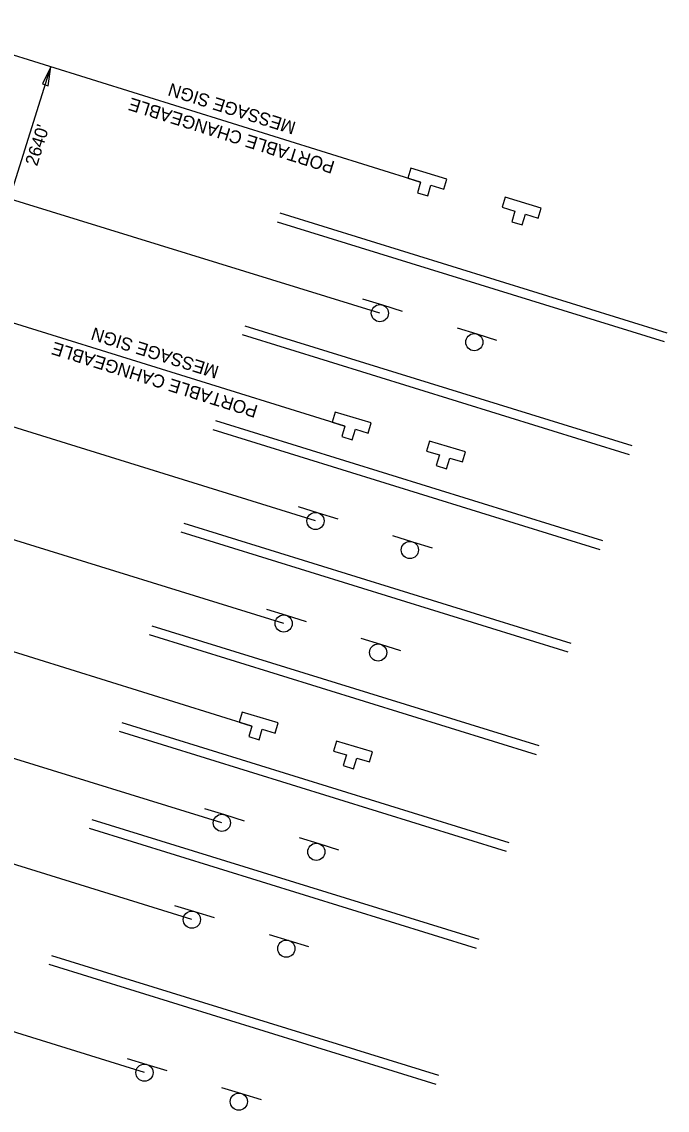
# Model space of a CAD drawing. Extents: x 2135767 to 2151731, y 141839 to 175894.
# Drawn here: x 2151203 to 2151504, y 148873 to 149380 of the extents above; entities that cross this region are included whole.
import ezdxf

# ---------------------------------------------------------------- set-up
doc = ezdxf.new("R2010")
doc.units = 0
for name, color, linetype in [('Default', 7, 'Continuous'), ('PR_Dimensions', 7, 'Continuous'), ('PR_Dimensions_Phase', 7, 'Continuous'), ('PR_Traffic_Control_Devices_Temp', 7, 'Continuous'), ('PR_Traffic_Sign_Temp', 7, 'Continuous'), ('PR_Txt', 7, 'Continuous')]:
    doc.layers.add(name, color=color, linetype=linetype)

# ---------------------------------------------------------------- blocks, each defined once
blk = doc.blocks.new('Arrowhd')
at = {"layer": 'Default'}
blk.add_lwpolyline([(0.318, -0.053), (0.318, 0.053), (0, 0)], close=True, dxfattribs=at)
blk = doc.blocks.new('PR-TCSIGN_rev')
at = {"layer": 'Default'}
blk.add_lwpolyline([(-5.47, 0), (-1.58, 0), (-1.58, -3.22), (1.58, -3.22), (1.58, 0), (5.47, 0), (5.47, 3.06), (-5.47, 3.06)], close=True, dxfattribs=at)
blk.add_lwpolyline([(1.58, 0), (5.47, 0), (5.47, 3.06), (-5.47, 3.06), (-5.47, 0), (-1.58, 0), (-1.58, -3.22), (1.58, -3.22), (1.58, 0)], dxfattribs=at)

msp = doc.modelspace()

# ---------------------------------------------------------------- linework, layer by layer
at = {"layer": 'PR_Dimensions'}
msp.add_line((2151197.49, 149297.31), (2151216.87, 149358.8), dxfattribs=at)
at = {"layer": 'PR_Dimensions_Phase'}
for p, q in [((2151389.04, 149305.13), (2151149.5, 149379.8)), ((2151370.1, 149244.07), (2151070.02, 149336.62)), ((2151503.95, 149234.82), (2151323.67, 149290.64)), ((2151502.68, 149230.71), (2151322.37, 149286.54)), ((2151353.81, 149191.55), (2151123.89, 149262.85)), ((2151340.1, 149147.34), (2151058.89, 149234.74)), ((2151486.39, 149178.19), (2151306.07, 149234.02)), ((2151487.66, 149182.29), (2151307.38, 149238.11)), ((2151473.95, 149138.08), (2151293.66, 149193.9)), ((2151472.68, 149133.97), (2151292.36, 149189.8)), ((2151325.29, 149099.6), (2151125.02, 149161.69)), ((2151310.48, 149051.85), (2151016.6, 149143.16)), ((2151457.87, 149086.23), (2151277.55, 149142.06)), ((2151459.14, 149090.33), (2151278.85, 149146.15)), ((2151444.33, 149042.59), (2151264.05, 149098.41)), ((2151443.06, 149038.49), (2151262.74, 149094.31)), ((2151296.5, 149006.77), (2151104.82, 149066.04)), ((2151430.35, 148997.51), (2151250.06, 149053.33)), ((2151429.08, 148993.4), (2151248.76, 149049.23)), ((2151282.52, 148961.69), (2151023.58, 149042.07)), ((2151416.36, 148952.42), (2151236.08, 149008.24)), ((2151415.09, 148948.32), (2151234.78, 149004.15)), ((2151260.42, 148890.44), (2151051.8, 148955.29)), ((2151397.63, 148889.08), (2151217.34, 148944.9)), ((2151396.36, 148884.98), (2151216.04, 148940.81))]:
    msp.add_line(p, q, dxfattribs=at)
at = {"layer": 'PR_Traffic_Sign_Temp'}
for p, q in [((2151362.06, 149250.75), (2151371.28, 149247.91)), ((2151371.28, 149247.91), (2151380.51, 149245.07)), ((2151406.04, 149237.25), (2151415.26, 149234.41)), ((2151415.26, 149234.41), (2151424.48, 149231.57)), ((2151332.06, 149154.01), (2151341.28, 149151.17)), ((2151341.28, 149151.17), (2151350.5, 149148.33)), ((2151376.03, 149140.51), (2151385.25, 149137.67)), ((2151385.25, 149137.67), (2151394.48, 149134.83)), ((2151317.25, 149106.26), (2151326.47, 149103.42)), ((2151326.47, 149103.42), (2151335.69, 149100.58)), ((2151361.22, 149092.76), (2151370.44, 149089.93)), ((2151370.44, 149089.93), (2151379.67, 149087.09)), ((2151288.45, 149013.43), (2151297.67, 149010.59)), ((2151297.67, 149010.59), (2151306.9, 149007.75)), ((2151332.43, 148999.94), (2151341.65, 148997.1)), ((2151341.65, 148997.1), (2151350.88, 148994.26)), ((2151274.47, 148968.35), (2151283.69, 148965.51)), ((2151283.69, 148965.51), (2151292.92, 148962.67)), ((2151318.45, 148954.85), (2151327.67, 148952.02)), ((2151327.67, 148952.02), (2151336.89, 148949.18)), ((2151252.37, 148897.1), (2151261.59, 148894.26)), ((2151261.59, 148894.26), (2151270.82, 148891.42)), ((2151296.35, 148883.6), (2151305.57, 148880.77)), ((2151305.57, 148880.77), (2151314.79, 148877.93))]:
    msp.add_line(p, q, dxfattribs=at)
for centre in [(2151370.11, 149244.09), (2151414.08, 149230.59), (2151340.1, 149147.35), (2151384.08, 149133.85), (2151325.29, 149099.6), (2151369.27, 149086.1), (2151296.5, 149006.77), (2151340.48, 148993.27), (2151282.52, 148961.69), (2151326.49, 148948.19), (2151260.42, 148890.44), (2151304.39, 148876.94)]:
    msp.add_circle(centre, 4, dxfattribs=at)

# ---------------------------------------------------------------- block references
at = {"layer": 'PR_Dimensions', "xscale": 27.559000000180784, "yscale": 27.559000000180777, "rotation": -107.4277226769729}
msp.add_blockref('Arrowhd', (2151216.87, 149358.8), dxfattribs=at)
at = {"layer": 'PR_Traffic_Control_Devices_Temp', "xscale": 1.5993550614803, "yscale": 1.5993550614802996, "rotation": -16.802196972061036}
for p in [(2151391.47, 149304.4), (2151435.45, 149290.91), (2151356.24, 149190.83), (2151400.22, 149177.33), (2151312.91, 149051.12), (2151356.89, 149037.63)]:
    msp.add_blockref('PR-TCSIGN_rev', p, dxfattribs=at)

# ---------------------------------------------------------------- texts
at = {"layer": 'PR_Txt'}
for s, rotation, p in [('MESSAGE SIGN', 162.5723, (2151331.39, 149332.93)), ('PORTABLE CHANGEABLE', 162.5723, (2151349.51, 149314.66)), ("2640'", 72.5723, (2151210.4, 149312.26)), ('MESSAGE SIGN', 162.5723, (2151295.55, 149219.23)), ('PORTABLE CAHNGEABLE', 162.5723, (2151313.68, 149200.97))]:
    msp.add_text(s, height=6, rotation=rotation, dxfattribs=at).set_placement(p)

doc.saveas('drawing.dxf')
